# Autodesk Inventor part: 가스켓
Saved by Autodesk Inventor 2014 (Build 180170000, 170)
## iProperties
Created: 2025-02
Part Number: 가스켓
Material: 스테인레스 스틸
Document SubType Name: Modeling
Designer: dg
Density: 8.08 g/cm^3
Appearance: 반연마
Mass: 33.5902 g
Surface Area: 93.1904 cm^2
Volume: 4.15721 cm^3
Author: jhkim
Creation Date: 2025-01-06
Sending System: Autodesk Inventor 2025
Preprocessor: ST-DEVELOPER v20
Author: dg
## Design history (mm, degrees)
node "가스켓1"
node "솔리드1"
node "기준1"
